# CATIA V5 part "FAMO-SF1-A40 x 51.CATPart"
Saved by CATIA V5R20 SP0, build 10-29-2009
Part number: FAMO-SF1-A40 x 51
Definition: NONE
Nomenclature: FAMO-SF1-A40 x 51
Source: Unknown
Description: FAMO-SF1-A40 x 51
Bounding box of the stored display mesh (mm): x -13 to 38, y -31.5 to 31.5, z -31.5 to 31.5
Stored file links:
  C:\Users\Utente\Desktop\IO LAVORO\3D X SITO CF\X SITO\FAMO\FAMO-SF1-A40 x 51.CATPart
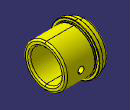
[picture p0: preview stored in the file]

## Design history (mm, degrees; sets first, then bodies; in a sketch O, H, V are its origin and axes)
Body1 "FAMO-SF1-A40 x 51" (main body)
  Solid1: solid without history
